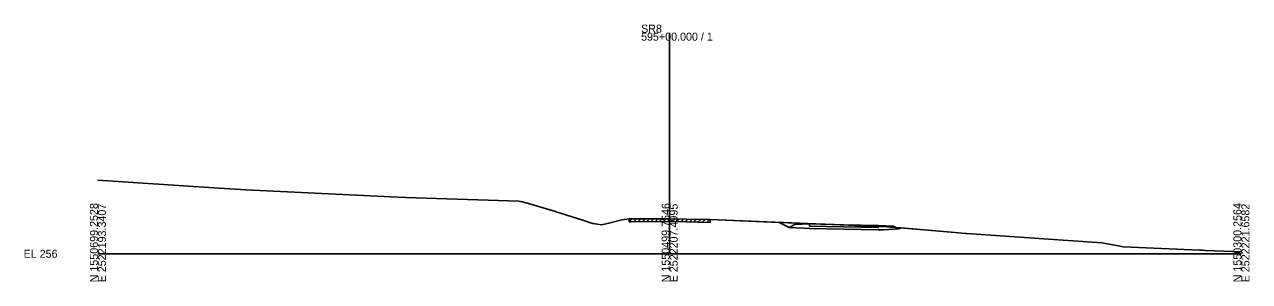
# Model space of a CAD drawing. Extents: x -26 to 2803, y -10 to 19537.
# Drawn here: x -25.7 to 402.8, y 4990.3 to 5080.1 of the extents above; entities that cross this region are included whole.
import ezdxf

# ---------------------------------------------------------------- set-up
doc = ezdxf.new("R2010")
doc.units = 0
for name, color, linetype in [('50', 7, 'Continuous'), ('XS_CELL', 7, 'Continuous'), ('XS_M_MULTI', 7, 'Continuous'), ('XS_M_SHAPES_EARTHWORK', 7, 'Continuous'), ('XS_P_FINISHED_GRADE', 7, 'Continuous'), ('XS_P_SUBGRADE_GRANULAR', 7, 'Continuous'), ('XS_P_SUBGRADE_PAVEMENT', 7, 'Continuous'), ('XS_X_GROUND', 7, 'Continuous')]:
    doc.layers.add(name, color=color, linetype=linetype)

msp = doc.modelspace()

# ---------------------------------------------------------------- linework, layer by layer
at = {"layer": '50'}
for p, q in [((185.89, 5011.15), (186.89, 5012.15)), ((185.89, 5011.15), (185.89, 5012.15)), ((185.89, 5011.15), (186.44, 5011.15)), ((186.44, 5011.15), (200, 5011.24)), ((187.39, 5011.16), (188.39, 5012.16)), ((188.89, 5011.17), (189.89, 5012.17)), ((190.39, 5011.18), (191.39, 5012.18)), ((191.89, 5011.19), (192.89, 5012.19)), ((193.39, 5011.2), (194.39, 5012.2)), ((194.89, 5011.2), (195.89, 5012.21)), ((196.39, 5011.21), (197.39, 5012.22)), ((197.89, 5011.22), (198.89, 5012.23)), ((199.39, 5011.23), (200.38, 5012.23)), ((200, 5011.24), (205.82, 5011.1)), ((200.89, 5011.22), (201.87, 5012.19)), ((202.39, 5011.18), (203.37, 5012.16)), ((203.89, 5011.15), (204.87, 5012.13)), ((205.39, 5011.11), (206.37, 5012.09)), ((205.82, 5011.1), (214.18, 5010.91)), ((206.89, 5011.08), (207.87, 5012.06)), ((208.39, 5011.04), (209.37, 5012.02)), ((209.89, 5011.01), (210.87, 5011.99)), ((211.39, 5010.97), (212.37, 5011.95)), ((212.89, 5010.94), (213.87, 5011.92)), ((214.18, 5011.91), (214.18, 5010.91))]:
    msp.add_line(p, q, dxfattribs=at)
at = {"layer": 'XS_CELL'}
for p, q in [((200, 5000), (200, 5077.24)), ((0, 5000), (200, 5000)), ((200, 5000), (400, 5000))]:
    msp.add_line(p, q, dxfattribs=at)
at = {"layer": 'XS_M_MULTI'}
for p, q in [((238.29, 5010.93), (241.78, 5009.2)), ((241.78, 5009.2), (243.8, 5010.2)), ((243.8, 5010.2), (248.85, 5010.4)), ((248.85, 5010.4), (260.97, 5010.13)), ((260.97, 5010.13), (273.09, 5009.85)), ((273.09, 5009.85), (278.13, 5009.65)), ((278.13, 5009.65), (280.15, 5008.65)), ((280.15, 5008.65), (280.93, 5009.04))]:
    msp.add_line(p, q, dxfattribs=at)
for points in [[(0, 5025.75), (40.49, 5023.02), (51.73, 5022.27), (66.27, 5021.58), (104.91, 5019.76), (107.75, 5019.66), (147.22, 5018.34), (148.43, 5018.09), (151.41, 5017.26), (160.06, 5014.71), (160.58, 5014.55), (161.85, 5014.15), (169.92, 5011.57), (171.93, 5010.93), (173.07, 5010.56), (176.19, 5010.12), (177.68, 5010.42), (178.75, 5010.65), (183.22, 5011.84), (185.89, 5012.15), (186.44, 5012.15), (200, 5012.24), (205.82, 5012.1), (214.18, 5011.91), (238.29, 5010.93)], [(280.93, 5009.04), (299.84, 5007.41), (303.52, 5007.08), (303.85, 5007.05), (351.17, 5003.8), (353.22, 5003.42), (358.77, 5002.41), (385.33, 5001.28), (386.08, 5001.24), (386.45, 5001.22), (387.47, 5001.18), (400, 5000.65)]]:
    msp.add_lwpolyline(points, dxfattribs=at)
at = {"layer": 'XS_M_SHAPES_EARTHWORK'}
for points in [[(248.85, 5010.4), (243.8, 5010.2), (241.78, 5009.2), (238.29, 5010.93), (254.39, 5010.28), (248.97, 5010.4)], [(260.97, 5008.63), (272.97, 5008.39), (274.97, 5008.35), (280.15, 5008.65), (279.06, 5009.2), (277.86, 5009.3), (277.2, 5009.33), (274.55, 5009.46), (274.02, 5009.48), (273.24, 5009.51), (272.97, 5009.53), (272.97, 5009.14), (260.97, 5009.38), (248.97, 5009.62), (248.97, 5010.4), (248.85, 5010.4), (243.8, 5010.2), (241.78, 5009.2), (246.97, 5008.91), (248.97, 5008.87)], [(262.39, 5009.95), (269.45, 5009.67), (271.96, 5009.57), (272.97, 5009.53), (272.97, 5009.14), (260.97, 5009.38), (248.97, 5009.62), (248.97, 5010.4), (254.39, 5010.28)], [(262.39, 5009.95), (269.45, 5009.67), (271.96, 5009.57), (272.97, 5009.53), (272.97, 5009.86), (260.97, 5010.13), (254.39, 5010.28)], [(272.97, 5009.53), (273.24, 5009.51), (274.02, 5009.48), (274.55, 5009.46), (277.2, 5009.33), (277.86, 5009.3), (279.06, 5009.2), (278.13, 5009.65), (273.09, 5009.85), (272.97, 5009.86)], [(279.06, 5009.2), (280.93, 5009.04), (280.15, 5008.65)]]:
    msp.add_lwpolyline(points, close=True, dxfattribs=at)
at = {"layer": 'XS_P_FINISHED_GRADE'}
for p, q in [((241.78, 5009.2), (238.29, 5010.93)), ((243.8, 5010.2), (241.78, 5009.2)), ((248.85, 5010.4), (243.8, 5010.2)), ((248.85, 5010.4), (260.97, 5010.13)), ((260.97, 5010.13), (273.09, 5009.85)), ((273.09, 5009.85), (278.13, 5009.65)), ((278.13, 5009.65), (280.15, 5008.65)), ((280.15, 5008.65), (280.93, 5009.04))]:
    msp.add_line(p, q, dxfattribs=at)
at = {"layer": 'XS_P_SUBGRADE_GRANULAR'}
for p, q in [((246.97, 5008.91), (241.78, 5009.2)), ((248.97, 5008.87), (246.97, 5008.91)), ((248.97, 5008.87), (260.97, 5008.63)), ((260.97, 5008.63), (272.97, 5008.39)), ((272.97, 5008.39), (274.97, 5008.35)), ((274.97, 5008.35), (280.15, 5008.65))]:
    msp.add_line(p, q, dxfattribs=at)
at = {"layer": 'XS_P_SUBGRADE_PAVEMENT'}
for p, q in [((248.97, 5009.62), (248.97, 5010.4)), ((248.97, 5009.62), (260.97, 5009.38)), ((272.97, 5009.14), (272.97, 5009.86)), ((260.97, 5009.38), (272.97, 5009.14))]:
    msp.add_line(p, q, dxfattribs=at)
at = {"layer": 'XS_X_GROUND'}
msp.add_lwpolyline([(0, 5025.75), (40.49, 5023.02), (51.73, 5022.27), (66.27, 5021.58), (104.91, 5019.76), (107.75, 5019.66), (147.22, 5018.34), (148.43, 5018.09), (151.41, 5017.26), (160.06, 5014.71), (160.58, 5014.55), (161.85, 5014.15), (169.92, 5011.57), (171.93, 5010.93), (173.07, 5010.56), (176.19, 5010.12), (177.68, 5010.42), (178.75, 5010.65), (183.22, 5011.84), (185.89, 5012.15), (186.44, 5012.15), (200, 5012.24), (205.82, 5012.1), (214.18, 5011.91), (262.39, 5009.95), (269.45, 5009.67), (271.96, 5009.57), (273.24, 5009.51), (274.02, 5009.48), (274.55, 5009.46), (277.2, 5009.33), (277.86, 5009.3), (299.84, 5007.41), (303.52, 5007.08), (303.85, 5007.05), (351.17, 5003.8), (353.22, 5003.42), (358.77, 5002.41), (385.33, 5001.28), (386.08, 5001.24), (386.45, 5001.22), (387.47, 5001.18), (400, 5000.65)], dxfattribs=at)

# ---------------------------------------------------------------- texts
at = {"layer": 'XS_CELL'}
for s, p in [('SR8', (190, 5077.24)), ('595+00.000 / 1', (190, 5074.44)), ('EL 256', (-26, 4998.6))]:
    msp.add_text(s, height=2.8, dxfattribs=at).set_placement(p)
for s, p in [('N 1550699.2528', (0, 4990)), ('E 2522193.3407', (2.8, 4990)), ('N 1550499.7546', (200, 4990)), ('E 2522207.4995', (202.8, 4990)), ('N 1550300.2564', (400, 4990)), ('E 2522221.6582', (402.8, 4990))]:
    msp.add_text(s, height=2.8, rotation=90, dxfattribs=at).set_placement(p)

doc.saveas('drawing.dxf')
